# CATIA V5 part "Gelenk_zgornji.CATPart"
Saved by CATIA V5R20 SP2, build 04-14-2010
Part number: Gelenk_zgornji
Bounding box of the stored display mesh (mm): x -4.8 to 4.8, y 0 to 25, z -29.795 to 29.795
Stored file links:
  C:\Documents and Settings\Administrator\My Documents\Hobi_dokumenti\CAD_CNC\Clap_CATIA\Gelenk_zgornji.CATPart
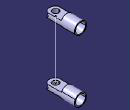
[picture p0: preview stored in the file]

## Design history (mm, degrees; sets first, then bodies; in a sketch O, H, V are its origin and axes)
Set1
  Point1: type Center, Curve edge [face of Pocket1 from Sketch2.L5 | face of Pocket2 from Sketch3.A1]
  Point2: type Center, Curve edge [face of Mirror1 | face of Mirror1]
  Line1: type PtPt, FirstPoint Point2, SecondPoint Point1
Body1 (main body)
  Sketch1 on xy-plane, origin (0, 0, 0), H (1, 0, 0), V (0, 1, 0)
    line L1 (0, 0) -> (-4.8, 0)
    line L2 (-4.8, 0) -> (-4.8, 25)
    line L3 (-4.8, 25) -> (0, 25)
    line L4 (0, 25) -> (0, 0)
    point P1 (-4.8, 0)
    point P3 (0, 25)
    distance O P1 = 4.8
    distance P3 O = 25
    horizontal: L1 H, L3 H
    vertical: L2 V, L4 V
    perpendicularity: L1 L2
  Shaft1: profile Sketch1, axis Sketch1.L4, angle 360
  Translate1: ToTransfor Shaft1, Direction xy-plane, Length 25
  Sketch2 on yz-plane, origin (0, 0, 0), H (0, 1, 0), V (0, 0, 1)
    line L1 (-3.9957, 30.9) -> (14, 30.9)
    line L2 (14, 30.9) -> (14, 26.9)
    line L3 (14, 26.9) -> (-3.9957, 26.9)
    line L4 (-3.9957, 26.9) -> (-3.9957, 30.9)
    point P5 (-3.9957, 23.1)
    line L5 (-3.9957, 23.1) -> (14, 23.1)
    line L6 (14, 23.1) -> (14, 19.1)
    line L7 (14, 19.1) -> (-3.9957, 19.1)
    line L8 (-3.9957, 19.1) -> (-3.9957, 23.1)
    point P7 (14, 19.1)
    reference projected line E1 through (0, 25) direction (1, 0) from axis of face of Shaft1 from Sketch1.L2
    reference projected line E2 through (0, 25) direction (1, 0) from axis of face of Shaft1 from Sketch1.L2
    reference projected line E3 (0, 29.8) -> (0, 20.2) from edge [face of Shaft1 from Sketch1.L1 | face of Shaft1 from Sketch1.L2]
    distance E1 L5 = 1.9
    distance E2 L3 = 1.9
    distance E3 L2 = 14
    length L8 = 4
    length L4 = 4
    horizontal: L1 H, L3 H, L5 H, L7 H
    vertical: L2 V, L4 V, L6 V, L8 V
    coincidence: P5 L4, P7 L2
  Pocket1: profile Sketch2, direction (1, 0, 0), length 20, mirrored extent
  Sketch3 on xy-plane, origin (0, 0, 0), H (1, 0, 0), V (0, 1, 0)
    circle A1 centre (0, 4.9462) radius 2.5
    point P1 (0, 4.9462)
    arc A2 centre (0, 4.9462) radius 5 from (-5, 4.9462) to (5, 4.9462) ccw
    line L1 (8.2326, 4.9462) -> (5, 4.9462)
    line L2 (-8.288, 4.9462) -> (-8.288, -1.7558)
    line L3 (-8.288, -1.7558) -> (8.2326, -1.7558)
    line L4 (8.2326, -1.7558) -> (8.2326, 4.9462)
    point P6 (-5, 4.9462)
    line L5 (-5, 4.9462) -> (-8.288, 4.9462)
    radius A1 = 2.5
    radius A2 = 5
    coincidence: P1 V, L1 P6
    horizontal: L1 H, L3 H, L5 H
    vertical: L2 V, L4 V
  Pocket2: profile Sketch3, direction (0, 0, 1), through (limit type 6)
  Mirror1: of the body so far, about xy-plane
  Sketch4 on face of Mirror1, origin (0, 25, 0), H (-1, 0, 0), V (0, 0, 1)
    circle A1 centre (0, 25) radius 4
    point P1 (0, 25)
    circle A2 centre (0, -25) radius 4
    point P2 (0, -25)
    reference intersected line E1 through (0, 0) direction (-1, 0) from xy-plane
    reference intersected line E2 through (0, 0) direction (0, -1) from yz-plane
    radius A1 = 4
    radius A2 = 4
    distance P2 H = 25
    distance P1 H = 25
    coincidence: P1 V, P2 V, E2 P1
    vertical: E2 V
    horizontal: E1 H
  Pocket3: profile Sketch4, direction (0, -1, 0), length 10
